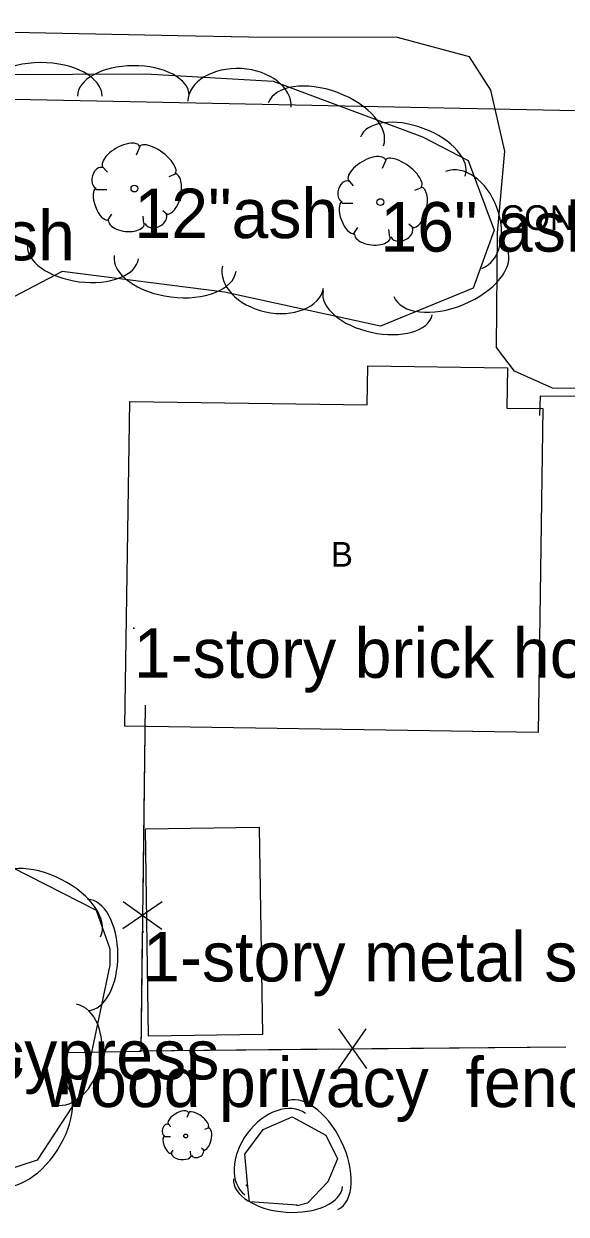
# Model space of a CAD drawing. Extents: x 1802180 to 1804859, y 572524 to 575172.
# Drawn here: x 1803636.9 to 1803691.6, y 574622.9 to 574743 of the extents above; entities that cross this region are included whole.
import ezdxf

# ---------------------------------------------------------------- set-up
doc = ezdxf.new("R2010")
doc.units = 0
for name, color, linetype in [('S_BUILDING', 7, 'Continuous'), ('S_BUILDING_ANNOT', 7, 'Continuous'), ('S_DRIVEWAY', 7, 'Continuous'), ('S_DRIVEWAY_ANNOT', 7, 'Continuous'), ('S_FENCE', 7, 'Continuous'), ('S_MSC_PT_SYM', 7, 'Continuous'), ('S_SANITARY_SEWER', 7, 'Continuous'), ('S_SURVEY_TEXT_ANNOT', 7, 'Continuous'), ('S_TREE', 7, 'Continuous'), ('S_TREE_ANNOT', 7, 'Continuous')]:
    doc.layers.add(name, color=color, linetype=linetype)

msp = doc.modelspace()

# ---------------------------------------------------------------- linework, layer by layer
at = {"layer": 'S_BUILDING'}
for points in [[(1803688.77, 574671.49), (1803647.06, 574672.11), (1803647.55, 574704.91), (1803671.53, 574704.56), (1803671.59, 574708.51), (1803685.68, 574708.3), (1803685.62, 574704.24), (1803689.26, 574704.19), (1803688.77, 574671.49)], [(1803660.63, 574661.93), (1803660.94, 574640.99), (1803649.44, 574640.82), (1803649.13, 574661.76), (1803660.63, 574661.93)]]:
    msp.add_lwpolyline(points, dxfattribs=at)
at = {"layer": 'S_DRIVEWAY'}
msp.add_lwpolyline([(1803707.25, 574706.09), (1803690.24, 574706.25), (1803686.4, 574707.95), (1803684.56, 574710.36), (1803684.67, 574721.94), (1803685.41, 574730.17), (1803684, 574736.32), (1803681.84, 574739.69), (1803674.57, 574741.63), (1803659.57, 574741.67), (1803652.42, 574741.82), (1803637.42, 574742.1), (1803622.67, 574742.45), (1803619.88, 574742.67), (1803604.87, 574742.85), (1803591.6, 574742.93), (1803577.5, 574743.03), (1803570.55, 574742.88), (1803555.57, 574742.2), (1803546.02, 574737.88), (1803540.9, 574733.24)], dxfattribs=at)
at = {"layer": 'S_FENCE'}
for p, q in [((1803650.84, 574654.38), (1803646.85, 574651.66)), ((1803646.89, 574654.43), (1803650.8, 574651.61)), ((1803668.61, 574641.55), (1803671.45, 574637.57)), ((1803668.64, 574637.54), (1803671.41, 574641.58)), ((1803648.49, 574639.36), (1803691.56, 574639.76))]:
    msp.add_line(p, q, dxfattribs=at)
for points in [[(1803688.95, 574703.49), (1803689, 574705.48), (1803717.28, 574705.21)], [(1803688.95, 574703.49), (1803689, 574705.48), (1803700.76, 574705.37)], [(1803649.11, 574674.25), (1803648.67, 574639.27), (1803641.19, 574639.14)], [(1803649.11, 574674.25), (1803648.87, 574654.95)], [(1803648.82, 574651.09), (1803648.67, 574639.27), (1803641.19, 574639.14)], [(1803648.49, 574639.36), (1803668.07, 574639.54)], [(1803671.99, 574639.58), (1803691.56, 574639.76)]]:
    msp.add_lwpolyline(points, dxfattribs=at)
at = {"layer": 'S_MSC_PT_SYM'}
for points in [[(1803647.96, 574682), (1803647.96, 574682.05), (1803647.96, 574682), (1803647.91, 574682), (1803647.96, 574682), (1803647.96, 574681.95), (1803647.96, 574682), (1803648.01, 574682)], [(1803648.9, 574651.35), (1803648.9, 574651.4), (1803648.9, 574651.35), (1803648.85, 574651.35), (1803648.9, 574651.35), (1803648.9, 574651.3), (1803648.9, 574651.35), (1803648.95, 574651.35)]]:
    msp.add_lwpolyline(points, dxfattribs=at)
at = {"layer": 'S_SANITARY_SEWER'}
msp.add_line((1803582.81, 574736.49), (1803914.33, 574729.75), dxfattribs=at)
at = {"layer": 'S_TREE'}
for p, q in [((1803648.58, 574730.63), (1803648.19, 574729.78)), ((1803673.41, 574729.27), (1803673.02, 574728.42)), ((1803644.78, 574728.62), (1803645.29, 574728.04)), ((1803652.14, 574727.84), (1803651.49, 574727.57)), ((1803669.61, 574727.26), (1803670.11, 574726.68)), ((1803676.97, 574726.48), (1803676.31, 574726.21)), ((1803644.12, 574726.29), (1803645.25, 574726.29)), ((1803651.37, 574723.74), (1803650.9, 574724.16)), ((1803668.95, 574724.93), (1803670.08, 574724.93)), ((1803645.29, 574723.12), (1803645.75, 574723.81)), ((1803648.97, 574722.85), (1803648.89, 574723.62)), ((1803676.2, 574722.38), (1803675.73, 574722.8)), ((1803670.11, 574721.76), (1803670.58, 574722.45)), ((1803673.8, 574721.48), (1803673.72, 574722.26)), ((1803653.51, 574633.09), (1803653.3, 574632.62)), ((1803651.42, 574631.98), (1803651.69, 574631.66)), ((1803655.48, 574631.55), (1803655.11, 574631.4)), ((1803651.05, 574630.7), (1803651.67, 574630.7)), ((1803651.69, 574628.95), (1803651.95, 574629.33)), ((1803653.73, 574628.8), (1803653.68, 574629.22)), ((1803655.05, 574629.29), (1803654.79, 574629.52))]:
    msp.add_line(p, q, dxfattribs=at)
for points in [[(1803612.28, 574715.45), (1803608.3, 574726.13), (1803616.93, 574733.76), (1803634.39, 574737.92), (1803649.16, 574737.99), (1803662.04, 574737.24), (1803677.1, 574731.63), (1803681.72, 574729.22), (1803684.33, 574722.18), (1803682.2, 574716.35), (1803672.87, 574712.5), (1803657.13, 574715.95), (1803640.72, 574718.03), (1803633.7, 574714.34), (1803625.87, 574708.47), (1803619.63, 574709.39), (1803614.33, 574712.34), (1803612.28, 574715.45)], [(1803567.31, 574659.26), (1803608.23, 574660.68), (1803627.05, 574662.27), (1803644.17, 574653.55), (1803645.55, 574649.63), (1803645.55, 574648), (1803642.91, 574635.52), (1803638.2, 574628.32), (1803629.41, 574625.43), (1803607.59, 574625.72), (1803578.59, 574627.47), (1803564.73, 574635.12), (1803561.13, 574649.88), (1803567.31, 574659.26)], [(1803659.46, 574625.62), (1803659.17, 574628.91), (1803661.03, 574631.41), (1803663.96, 574632.67), (1803667.35, 574630.82), (1803668.51, 574628.43), (1803667.55, 574626.11), (1803665.51, 574623.97), (1803664.45, 574623.69), (1803664.45, 574623.78), (1803659.64, 574624.11), (1803659.46, 574625.62), (1803659.28, 574625.8)]]:
    msp.add_lwpolyline(points, dxfattribs=at)
for centre, radius in [((1803648.02, 574726.39), 0.341), ((1803672.85, 574725.03), 0.341), ((1803653.2, 574630.75), 0.188)]:
    msp.add_circle(centre, radius, dxfattribs=at)
for centre, major_axis, ratio, start_param, end_param in [((1803638.56, 574735.7), (-6.2, -0.03), 0.55008, 3.141593, 6.283185), ((1803647.92, 574735.75), (-5.64, -0.03), 0.540699, 3.141593, 6.283185), ((1803658.62, 574734.92), (-5.22, 0.3), 0.685311, 3.141593, 6.283185), ((1803667.35, 574732.88), (-5.81, 2.16), 0.55008, 3.141593, 6.283185), ((1803676.12, 574729.61), (-5.29, 1.97), 0.540699, 3.141593, 6.283185), ((1803646.69, 574729.59), (1.86, 1.08), 0.471018, 0, 3.141593), ((1803650.34, 574729.27), (-1.81, 1.36), 0.405113, 3.141593, 6.283186), ((1803671.51, 574728.23), (1.86, 1.08), 0.471018, 0, 3.141593), ((1803675.17, 574727.91), (-1.81, 1.36), 0.405113, 3.141593, 6.283186), ((1803681.26, 574723.23), (-1.82, 4.9), 0.685311, 3.141593, 6.283185), ((1803644.45, 574727.48), (0.31, 1.03), 0.646762, 0, 3.141593), ((1803651.7, 574725.86), (0.46, 2.04), 0.482994, 3.141593, 6.283185), ((1803644.76, 574724.83), (-0.61, 1.6), 0.420543, 6.283185, 9.424777), ((1803669.28, 574726.12), (0.31, 1.03), 0.646762, 0, 3.141593), ((1803676.52, 574724.5), (0.46, 2.04), 0.482994, 3.141593, 6.283185), ((1803669.59, 574723.47), (-0.61, 1.6), 0.420543, 6.283185, 9.424777), ((1803647.22, 574723.04), (-1.83, 0.19), 0.529943, 0, 3.141593), ((1803650.17, 574723.34), (1.09, 0.46), 0.711534, 3.141592, 6.283185), ((1803672.05, 574721.68), (-1.83, 0.19), 0.529943, 0, 3.141593), ((1803675, 574721.98), (1.09, 0.46), 0.711534, 3.141592, 6.283185), ((1803642.84, 574720.02), (5.6, -0.71), 0.540699, 3.141593, 6.283185), ((1803652.13, 574718.84), (6.15, -0.78), 0.55008, 3.141593, 6.283185), ((1803679.95, 574717.84), (5.73, 2.36), 0.55008, 3.141593, 6.283185), ((1803662.01, 574717.45), (5.11, -1.12), 0.685311, 3.141593, 6.283185), ((1803672.58, 574714.86), (5.51, -1.21), 0.540699, 3.141593, 6.283185), ((1803639.11, 574653.64), (-5.48, 2.79), 0.55008, 3.141593, 6.283185), ((1803643.33, 574649.03), (-0.03, 5.6), 0.540699, 3.141593, 6.283185), ((1803641.09, 574638.97), (1.08, 5.08), 0.685311, 3.141593, 6.283185), ((1803637.38, 574631.12), (3.36, 5.15), 0.55008, 3.141593, 6.283185), ((1803662.23, 574628.91), (-3.05, -4.11), 0.685311, 3.141593, 6.283185), ((1803665.91, 574628.76), (-2.66, 5.45), 0.55008, 3.141593, 6.283185), ((1803652.47, 574632.52), (1.02, 0.6), 0.471018, 0, 3.141593), ((1803654.48, 574632.34), (-1, 0.75), 0.405113, 3.141593, 6.283186), ((1803651.23, 574631.35), (0.168, 0.567), 0.646762, 0, 3.141593), ((1803655.23, 574630.46), (0.25, 1.13), 0.482994, 3.141593, 6.283185), ((1803651.4, 574629.89), (-0.337, 0.88), 0.420543, 6.283185, 9.424777), ((1803654.39, 574629.07), (0.602, 0.255), 0.711534, 3.141592, 6.283185), ((1803652.76, 574628.91), (-1.01, 0.11), 0.529943, 0, 3.141593), ((1803663.53, 574626.04), (5.51, -0.38), 0.540699, 3.141593, 6.283185)]:
    msp.add_ellipse(centre, major_axis=major_axis, ratio=ratio, start_param=start_param, end_param=end_param, dxfattribs=at)

# ---------------------------------------------------------------- texts
at = {"layer": 'S_BUILDING_ANNOT'}
msp.add_text('B', height=2.5, dxfattribs=at).set_placement((1803667.85, 574688.22))
at = {"layer": 'S_DRIVEWAY_ANNOT'}
msp.add_text('CONC DRIVEWAY', height=2.5, dxfattribs=at).set_placement((1803684.95, 574722.21))
at = {"layer": 'S_SURVEY_TEXT_ANNOT'}
for s, p in [('1-story brick house ', (1803647.96, 574677)), ('1-story metal shed ', (1803648.9, 574646.35)), ("6' wood privacy  fence ", (1803631.86, 574633.67))]:
    msp.add_text(s, height=5, dxfattribs=at).set_placement(p)
at = {"layer": 'S_TREE_ANNOT'}
for s, p in [('12"ash ', (1803648.02, 574721.39)), ('16" ash ', (1803672.85, 574720.03)), ('12"ash ', (1803621.43, 574719.15)), ('18" cypress ', (1803621.89, 574636.46))]:
    msp.add_text(s, height=5, dxfattribs=at).set_placement(p)

doc.saveas('drawing.dxf')
